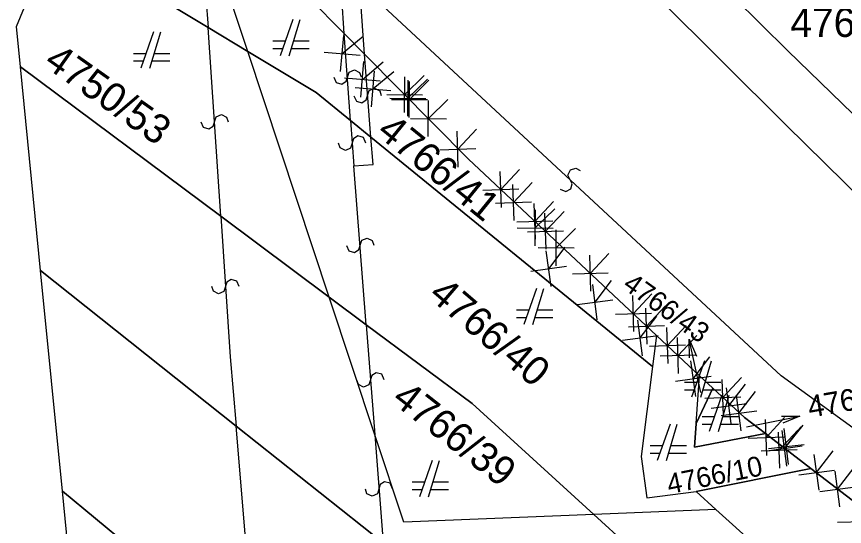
# Model space of a CAD drawing. Extents: x -266179 to -264727, y -1243225 to -1241702.
# Drawn here: x -264922.78 to -264877.21, y -1242480.52 to -1242452.44 of the extents above; entities that cross this region are included whole.
import ezdxf

# ---------------------------------------------------------------- set-up
doc = ezdxf.new("R2010")
doc.units = 0
for name, color, linetype in [('Vrstva 1', 7, 'Continuous'), ('Vrstva 2', 7, 'Continuous'), ('Vrstva 21', 7, 'Continuous')]:
    doc.layers.add(name, color=color, linetype=linetype)

msp = doc.modelspace()

# ---------------------------------------------------------------- linework, layer by layer
at = {"layer": 'Vrstva 1'}
for p, q in [((-264911.7, -1242446.34), (-264904.74, -1242453.38)), ((-264922.78, -1242452.99), (-264920.72, -1242447.94)), ((-264912.24, -1242453.04), (-264920.72, -1242447.94)), ((-264920.72, -1242447.94), (-264912.24, -1242453.04)), ((-264910.05, -1242454.36), (-264911.39, -1242450.32)), ((-264880.33, -1242454.34), (-264883.36, -1242451.33)), ((-264907.57, -1242452.6), (-264908.27, -1242454.6)), ((-264907.77, -1242454.6), (-264907.17, -1242452.6)), ((-264922.56, -1242455.22), (-264922.78, -1242452.99)), ((-264915.24, -1242453.29), (-264915.94, -1242455.29)), ((-264915.44, -1242455.29), (-264914.84, -1242453.29)), ((-264910.05, -1242454.36), (-264912.24, -1242453.04)), ((-264912.24, -1242453.04), (-264910.05, -1242454.36)), ((-264904.74, -1242453.38), (-264903.63, -1242454.51)), ((-264907.99, -1242453.8), (-264908.67, -1242453.8)), ((-264908.67, -1242454.2), (-264908.13, -1242454.2)), ((-264907.65, -1242454.2), (-264906.67, -1242454.2)), ((-264906.67, -1242453.8), (-264907.53, -1242453.8)), ((-264915.66, -1242454.49), (-264916.34, -1242454.49)), ((-264914.34, -1242454.49), (-264915.2, -1242454.49)), ((-264906.29, -1242456.62), (-264910.05, -1242454.36)), ((-264905.57, -1242467.9), (-264910.05, -1242454.36)), ((-264910.05, -1242454.36), (-264906.29, -1242456.62)), ((-264903.63, -1242454.51), (-264897.9, -1242460.3)), ((-264874.87, -1242459.63), (-264880.33, -1242454.34)), ((-264916.34, -1242454.89), (-264915.8, -1242454.89)), ((-264915.32, -1242454.89), (-264914.34, -1242454.89)), ((-264911.54, -1242463.44), (-264922.56, -1242455.22)), ((-264921.46, -1242466.43), (-264922.56, -1242455.22)), ((-264922.56, -1242455.22), (-264911.54, -1242463.44)), ((-264904.39, -1242458.17), (-264906.29, -1242456.62)), ((-264906.29, -1242456.62), (-264904.39, -1242458.17)), ((-264903.28, -1242459.08), (-264904.39, -1242458.17)), ((-264904.39, -1242458.17), (-264903.28, -1242459.08)), ((-264887.77, -1242471.72), (-264903.28, -1242459.08)), ((-264903.28, -1242459.08), (-264887.77, -1242471.72)), ((-264897.9, -1242460.3), (-264887.55, -1242470)), ((-264905.57, -1242467.9), (-264911.54, -1242463.44)), ((-264911.54, -1242463.44), (-264905.57, -1242467.9)), ((-264910.7, -1242474.99), (-264921.46, -1242466.43)), ((-264920.26, -1242478.58), (-264921.46, -1242466.43)), ((-264921.46, -1242466.43), (-264910.7, -1242474.99)), ((-264894.16, -1242467.41), (-264894.86, -1242469.41)), ((-264894.36, -1242469.41), (-264893.76, -1242467.41)), ((-264903.53, -1242469.42), (-264905.57, -1242467.9)), ((-264903.06, -1242475.48), (-264905.57, -1242467.9)), ((-264905.57, -1242467.9), (-264903.53, -1242469.42)), ((-264894.58, -1242468.61), (-264895.26, -1242468.61)), ((-264893.26, -1242468.61), (-264894.12, -1242468.61)), ((-264895.26, -1242469.01), (-264894.72, -1242469.01)), ((-264894.24, -1242469.01), (-264893.26, -1242469.01)), ((-264897.71, -1242473.76), (-264903.53, -1242469.42)), ((-264903.53, -1242469.42), (-264897.71, -1242473.76)), ((-264887.55, -1242470), (-264887.77, -1242471.72)), ((-264887.55, -1242470), (-264885.18, -1242472.22)), ((-264885.736, -1242471.23), (-264885.756, -1242470.21)), ((-264884.92, -1242471.4), (-264885.62, -1242473.4)), ((-264885.12, -1242473.4), (-264884.52, -1242471.4)), ((-264887.77, -1242471.72), (-264888.4, -1242476.67)), ((-264885.38, -1242474.86), (-264885.18, -1242472.22)), ((-264885.18, -1242472.22), (-264884.45, -1242472.9)), ((-264885.34, -1242472.6), (-264886.02, -1242472.6)), ((-264884.02, -1242472.6), (-264884.88, -1242472.6)), ((-264886.02, -1242473), (-264885.48, -1242473)), ((-264885.38, -1242474.86), (-264884.45, -1242472.9)), ((-264884.45, -1242472.9), (-264885.38, -1242474.86)), ((-264885, -1242473), (-264884.02, -1242473)), ((-264883.95, -1242473.29), (-264884.65, -1242475.29)), ((-264884.45, -1242472.9), (-264882.72, -1242474.52)), ((-264884.15, -1242475.29), (-264883.55, -1242473.29)), ((-264891.01, -1242479.86), (-264897.71, -1242473.76)), ((-264897.71, -1242473.76), (-264891.01, -1242479.86)), ((-264884.37, -1242474.49), (-264885.05, -1242474.49)), ((-264883.05, -1242474.49), (-264883.91, -1242474.49)), ((-264882.72, -1242474.52), (-264881.55, -1242475.41)), ((-264880.676, -1242474.447), (-264879.657, -1242474.45)), ((-264902.6, -1242481.43), (-264910.7, -1242474.99)), ((-264910.7, -1242474.99), (-264902.6, -1242481.43)), ((-264886.81, -1242474.89), (-264887.51, -1242476.89)), ((-264887.01, -1242476.89), (-264886.41, -1242474.89)), ((-264885.47, -1242476.16), (-264885.38, -1242474.86)), ((-264885.38, -1242474.86), (-264885.47, -1242476.16)), ((-264885.05, -1242474.89), (-264884.51, -1242474.89)), ((-264884.03, -1242474.89), (-264883.05, -1242474.89)), ((-264901.47, -1242480.29), (-264903.06, -1242475.48)), ((-264881.55, -1242475.41), (-264885.47, -1242476.16)), ((-264885.47, -1242476.16), (-264881.55, -1242475.41)), ((-264881.55, -1242475.41), (-264879.06, -1242477.33)), ((-264887.23, -1242476.09), (-264887.91, -1242476.09)), ((-264887.91, -1242476.49), (-264887.37, -1242476.49)), ((-264886.89, -1242476.49), (-264885.91, -1242476.49)), ((-264885.91, -1242476.09), (-264886.77, -1242476.09)), ((-264899.9, -1242476.89), (-264900.6, -1242478.89)), ((-264900.1, -1242478.89), (-264899.5, -1242476.89)), ((-264888.4, -1242476.67), (-264888.08, -1242478.95)), ((-264879.06, -1242477.33), (-264885.37, -1242478.6)), ((-264885.37, -1242478.6), (-264879.06, -1242477.33)), ((-264879.06, -1242477.33), (-264876.54, -1242479.26)), ((-264900.32, -1242478.09), (-264901, -1242478.09)), ((-264899, -1242478.09), (-264899.86, -1242478.09)), ((-264909.67, -1242487.32), (-264920.26, -1242478.58)), ((-264919.26, -1242488.75), (-264920.26, -1242478.58)), ((-264920.26, -1242478.58), (-264909.67, -1242487.32)), ((-264901, -1242478.49), (-264900.46, -1242478.49)), ((-264899.98, -1242478.49), (-264899, -1242478.49)), ((-264888.08, -1242478.95), (-264885.37, -1242478.6)), ((-264885.37, -1242478.6), (-264884.28, -1242479.58)), ((-264884.28, -1242479.58), (-264891.01, -1242479.86)), ((-264884.28, -1242479.58), (-264868.22, -1242494.08)), ((-264891.01, -1242479.86), (-264901.47, -1242480.29)), ((-264871.4, -1242497.72), (-264891.01, -1242479.86)), ((-264891.01, -1242479.86), (-264871.4, -1242497.72))]:
    msp.add_line(p, q, dxfattribs=at)
for points in [[(-264885.11, -1242473.14), (-264885.756, -1242470.21), (-264885.345, -1242471.144)], [(-264882.6, -1242475.03), (-264879.657, -1242474.45), (-264880.599, -1242474.839)]]:
    msp.add_lwpolyline(points, dxfattribs=at)
at = {"layer": 'Vrstva 2'}
for p, q in [((-264896.98, -1242441.91), (-264880.42, -1242458.43)), ((-264904.74, -1242453.38), (-264905.01, -1242449.63)), ((-264912.4, -1242450.74), (-264912.24, -1242453.04)), ((-264903.63, -1242454.51), (-264903.91, -1242450.65)), ((-264880.7, -1242472.22), (-264903.91, -1242450.65)), ((-264911.54, -1242463.44), (-264912.24, -1242453.04)), ((-264904.39, -1242458.17), (-264904.74, -1242453.38)), ((-264903.28, -1242459.08), (-264903.63, -1242454.51)), ((-264904.39, -1242458.17), (-264904.21, -1242460.66)), ((-264880.42, -1242458.43), (-264867.27, -1242471.37)), ((-264903.16, -1242460.59), (-264903.28, -1242459.08)), ((-264904.21, -1242460.66), (-264903.16, -1242460.59)), ((-264903.53, -1242469.42), (-264904.21, -1242460.66)), ((-264911.54, -1242463.44), (-264911.02, -1242471.18)), ((-264903.53, -1242469.42), (-264903.06, -1242475.48)), ((-264911.02, -1242471.18), (-264910.7, -1242474.99)), ((-264871.89, -1242478.65), (-264880.7, -1242472.22)), ((-264909.67, -1242487.32), (-264910.7, -1242474.99)), ((-264903.06, -1242475.48), (-264902.6, -1242481.43))]:
    msp.add_line(p, q, dxfattribs=at)
for points in [[(-264905.317, -1242455.78), (-264905.184, -1242456.081), (-264904.877, -1242456.169), (-264904.638, -1242456.011), (-264904.475, -1242455.498), (-264904.183, -1242455.376), (-264903.902, -1242455.516), (-264903.813, -1242455.77)], [(-264904.207, -1242456.802), (-264904.073, -1242457.103), (-264903.766, -1242457.19), (-264903.527, -1242457.031), (-264903.366, -1242456.517), (-264903.074, -1242456.395), (-264902.793, -1242456.534), (-264902.703, -1242456.788)], [(-264912.642, -1242458.24), (-264912.511, -1242458.542), (-264912.204, -1242458.632), (-264911.964, -1242458.476), (-264911.798, -1242457.963), (-264911.506, -1242457.843), (-264911.226, -1242457.985), (-264911.138, -1242458.24)], [(-264903.548, -1242459.41), (-264903.681, -1242459.109), (-264903.988, -1242459.021), (-264904.227, -1242459.179), (-264904.39, -1242459.692), (-264904.682, -1242459.814), (-264904.963, -1242459.674), (-264905.052, -1242459.42)], [(-264892.852, -1242461.95), (-264892.55, -1242462.081), (-264892.265, -1242461.936), (-264892.198, -1242461.657), (-264892.428, -1242461.171), (-264892.297, -1242460.883), (-264891.996, -1242460.794), (-264891.758, -1242460.92)], [(-264904.622, -1242465.048), (-264904.488, -1242465.349), (-264904.18, -1242465.435), (-264903.942, -1242465.276), (-264903.781, -1242464.762), (-264903.49, -1242464.639), (-264903.208, -1242464.778), (-264903.118, -1242465.032)], [(-264910.528, -1242467.31), (-264910.659, -1242467.008), (-264910.965, -1242466.918), (-264911.206, -1242467.075), (-264911.372, -1242467.587), (-264911.664, -1242467.706), (-264911.945, -1242467.565), (-264912.032, -1242467.31)], [(-264902.543, -1242472.442), (-264902.677, -1242472.141), (-264902.985, -1242472.055), (-264903.223, -1242472.214), (-264903.384, -1242472.728), (-264903.675, -1242472.851), (-264903.957, -1242472.712), (-264904.047, -1242472.458)], [(-264902.078, -1242478.447), (-264902.212, -1242478.146), (-264902.52, -1242478.06), (-264902.758, -1242478.219), (-264902.919, -1242478.733), (-264903.21, -1242478.856), (-264903.492, -1242478.717), (-264903.582, -1242478.463)]]:
    msp.add_lwpolyline(points, dxfattribs=at)
at = {"layer": 'Vrstva 21'}
for p, q in [((-264911.7, -1242446.34), (-264904.74, -1242453.38)), ((-264904.74, -1242453.38), (-264911.7, -1242446.34)), ((-264904.943, -1242455.468), (-264904.772, -1242453.495)), ((-264904.857, -1242454.482), (-264903.709, -1242453.516)), ((-264904.74, -1242453.38), (-264903.63, -1242454.51)), ((-264903.63, -1242454.51), (-264904.74, -1242453.38)), ((-264905.844, -1242454.396), (-264903.871, -1242454.567)), ((-264903.63, -1242454.51), (-264897.9, -1242460.3)), ((-264897.9, -1242460.3), (-264903.63, -1242454.51)), ((-264903.835, -1242456.888), (-264903.656, -1242454.916)), ((-264903.745, -1242455.902), (-264902.594, -1242454.941)), ((-264903.246, -1242457.42), (-264903.081, -1242455.447)), ((-264903.164, -1242456.433), (-264902.018, -1242455.464)), ((-264904.731, -1242455.813), (-264902.76, -1242455.991)), ((-264901.422, -1242457.736), (-264901.412, -1242455.756)), ((-264901.417, -1242456.746), (-264900.351, -1242455.691)), ((-264901.244, -1242457.936), (-264901.226, -1242455.956)), ((-264901.235, -1242456.946), (-264900.165, -1242455.895)), ((-264901.162, -1242457.999), (-264901.15, -1242456.019)), ((-264901.156, -1242457.009), (-264900.089, -1242455.955)), ((-264904.15, -1242456.351), (-264902.177, -1242456.515)), ((-264902.407, -1242456.741), (-264900.427, -1242456.751)), ((-264902.225, -1242456.937), (-264900.245, -1242456.955)), ((-264902.146, -1242457.003), (-264900.166, -1242457.015)), ((-264900.118, -1242459.054), (-264900.108, -1242457.074)), ((-264900.113, -1242458.064), (-264899.047, -1242457.009)), ((-264901.103, -1242458.059), (-264899.123, -1242458.069)), ((-264898.464, -1242460.734), (-264898.529, -1242458.755)), ((-264898.496, -1242459.744), (-264897.471, -1242458.649)), ((-264899.485, -1242459.777), (-264897.507, -1242459.712)), ((-264897.9, -1242460.3), (-264887.55, -1242470)), ((-264887.55, -1242470), (-264897.9, -1242460.3)), ((-264896.095, -1242462.955), (-264896.16, -1242460.977)), ((-264896.128, -1242461.966), (-264895.103, -1242460.871)), ((-264897.117, -1242461.998), (-264895.138, -1242461.934)), ((-264895.392, -1242463.667), (-264895.462, -1242461.688)), ((-264895.427, -1242462.677), (-264894.405, -1242461.579)), ((-264896.416, -1242462.713), (-264894.438, -1242462.642)), ((-264894.221, -1242464.71), (-264894.286, -1242462.731)), ((-264894.253, -1242463.721), (-264893.228, -1242462.626)), ((-264894.239, -1242465.072), (-264894.22, -1242463.092)), ((-264894.229, -1242464.082), (-264893.159, -1242463.031)), ((-264893.636, -1242465.257), (-264893.701, -1242463.278)), ((-264893.669, -1242464.267), (-264892.644, -1242463.172)), ((-264895.243, -1242463.753), (-264893.264, -1242463.688)), ((-264895.219, -1242464.073), (-264893.24, -1242464.091)), ((-264893.084, -1242466.162), (-264893.074, -1242464.182)), ((-264893.079, -1242465.172), (-264892.013, -1242464.117)), ((-264894.658, -1242464.3), (-264892.679, -1242464.235)), ((-264893.488, -1242466.327), (-264892.579, -1242465.134)), ((-264894.069, -1242465.167), (-264892.089, -1242465.177)), ((-264893.355, -1242467.308), (-264893.621, -1242465.346)), ((-264891.164, -1242467.569), (-264891.229, -1242465.59)), ((-264891.197, -1242466.579), (-264890.172, -1242465.485)), ((-264894.469, -1242466.46), (-264892.507, -1242466.194)), ((-264892.186, -1242466.612), (-264890.207, -1242466.547)), ((-264890.812, -1242469.153), (-264891.067, -1242467.19)), ((-264890.94, -1242468.172), (-264890.024, -1242466.983)), ((-264888.796, -1242469.791), (-264888.861, -1242467.812)), ((-264888.829, -1242468.801), (-264887.803, -1242467.706)), ((-264891.921, -1242468.299), (-264889.958, -1242468.044)), ((-264889.818, -1242468.834), (-264887.839, -1242468.769)), ((-264888.072, -1242470.48), (-264888.143, -1242468.501)), ((-264888.107, -1242469.491), (-264887.085, -1242468.393)), ((-264888.319, -1242471.121), (-264888.579, -1242469.158)), ((-264888.449, -1242470.139), (-264887.537, -1242468.949)), ((-264889.097, -1242469.526), (-264887.118, -1242469.455)), ((-264886.921, -1242471.545), (-264886.986, -1242469.566)), ((-264886.954, -1242470.556), (-264885.929, -1242469.461)), ((-264889.43, -1242470.27), (-264887.467, -1242470.009)), ((-264887.55, -1242470), (-264885.18, -1242472.22)), ((-264885.18, -1242472.22), (-264887.55, -1242470)), ((-264886.337, -1242472.092), (-264886.402, -1242470.113)), ((-264886.37, -1242471.102), (-264885.344, -1242470.008)), ((-264887.943, -1242470.588), (-264885.965, -1242470.523)), ((-264887.359, -1242471.135), (-264885.38, -1242471.07)), ((-264885.397, -1242473.365), (-264885.663, -1242471.403)), ((-264885.53, -1242472.384), (-264884.622, -1242471.19)), ((-264886.511, -1242472.517), (-264884.549, -1242472.251)), ((-264885.18, -1242472.22), (-264884.45, -1242472.9)), ((-264884.45, -1242472.9), (-264885.18, -1242472.22)), ((-264883.869, -1242474.408), (-264883.934, -1242472.429)), ((-264883.901, -1242473.419), (-264882.876, -1242472.324)), ((-264883.567, -1242473.877), (-264882.655, -1242472.686)), ((-264884.45, -1242472.9), (-264882.72, -1242474.52)), ((-264882.72, -1242474.52), (-264884.45, -1242472.9)), ((-264883.437, -1242474.858), (-264883.697, -1242472.895)), ((-264882.892, -1242475.258), (-264883.146, -1242473.294)), ((-264883.019, -1242474.276), (-264882.103, -1242473.088)), ((-264884.891, -1242473.451), (-264882.912, -1242473.386)), ((-264884.548, -1242474.007), (-264882.585, -1242473.747)), ((-264884.001, -1242474.403), (-264882.037, -1242474.149)), ((-264882.72, -1242474.52), (-264881.55, -1242475.41)), ((-264881.55, -1242475.41), (-264882.72, -1242474.52)), ((-264881.487, -1242476.619), (-264881.558, -1242474.64)), ((-264881.523, -1242475.629), (-264880.501, -1242474.531)), ((-264880.294, -1242477.101), (-264880.528, -1242475.135)), ((-264880.51, -1242476.22), (-264879.598, -1242475.029)), ((-264880.411, -1242476.118), (-264879.484, -1242474.939)), ((-264882.512, -1242475.665), (-264880.533, -1242475.594)), ((-264881.55, -1242475.41), (-264879.06, -1242477.33)), ((-264879.06, -1242477.33), (-264881.55, -1242475.41)), ((-264880.768, -1242477.307), (-264880.833, -1242475.328)), ((-264880.8, -1242476.318), (-264879.775, -1242475.223)), ((-264880.379, -1242477.201), (-264880.64, -1242475.239)), ((-264881.394, -1242476.235), (-264879.428, -1242476.001)), ((-264881.79, -1242476.35), (-264879.811, -1242476.285)), ((-264881.491, -1242476.35), (-264879.528, -1242476.09)), ((-264878.74, -1242477.546), (-264877.831, -1242476.352)), ((-264878.607, -1242478.527), (-264878.873, -1242476.565)), ((-264879.721, -1242477.679), (-264877.759, -1242477.413)), ((-264879.06, -1242477.33), (-264876.54, -1242479.26)), ((-264876.54, -1242479.26), (-264879.06, -1242477.33)), ((-264877.591, -1242478.464), (-264876.676, -1242477.276)), ((-264877.464, -1242479.446), (-264877.718, -1242477.482)), ((-264878.573, -1242478.591), (-264876.609, -1242478.337)), ((-264877.592, -1242480.286), (-264875.613, -1242480.222))]:
    msp.add_line(p, q, dxfattribs=at)

# ---------------------------------------------------------------- texts
at = {"layer": 'Vrstva 1'}
for s, height, rotation, p in [('4766/49', 1.6, 0.1719, (-264880.181, -1242453.575)), ('4750/53', 1.6, 324.8098, (-264921.347, -1242455.134)), ('4766/41', 1.6, 320.9137, (-264903.03, -1242458.93)), ('4766/43', 1.1, 324.3514, (-264889.479, -1242467.373)), ('4766/40', 1.6, 319.424, (-264900.17, -1242467.89)), ('4766/44', 1.2, 9.9122, (-264879.118, -1242474.537)), ('4766/39', 1.6, 322.0023, (-264902.197, -1242473.659)), ('4766/10', 1.1, 11.4019, (-264886.859, -1242478.745))]:
    msp.add_text(s, height=height, rotation=rotation, dxfattribs=at).set_placement(p)

doc.saveas('drawing.dxf')
